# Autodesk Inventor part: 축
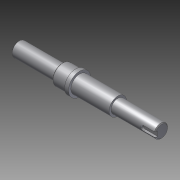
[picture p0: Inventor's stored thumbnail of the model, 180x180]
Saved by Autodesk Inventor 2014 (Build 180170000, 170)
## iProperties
Company: 한국ATC센터
Created: 2014-03
Part Number: 축
Document SubType Name: Modeling
Designer: KYOUNG IL JANG
Density: 1 g/cm^3
Material: 일반
Appearance: 기본값
Author: KYOUNG IL JANG
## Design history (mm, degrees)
sketch "스케치1"
  geometry: L1 (-102, 80)-(78, 80); L2 (-30.3, 106)-(-30.3, 54) reference; L3 (23, 99.7)-(23, 60.3) reference; L4 (-102, 80)-(-102, 89); L5 (-102, 89)-(-47, 89); L6 (-47, 89)-(-47, 92.5); L7 (-47, 92.5)-(-30, 92.5); L8 (-25, 94)-(-25, 91); L9 (-25, 91)-(23, 91); L10 (23, 91)-(23, 88.5); L11 (23, 88.5)-(78, 88.5); L12 (78, 88.5)-(78, 80); L13 (-30, 94)-(-25, 94); L14 (-31, 92.5)-(-44, 92.5) reference; L15 (-30, 105)-(-30, 55) reference; L16 (-30, 94)-(-30, 92.5); L17 (-68, 65.3)-(-68, 94.7) reference; L18 (-96, 89)-(-96, 85.5); L19 (-96, 85.5)-(-74, 85.5); L20 (-74, 85.5)-(-74, 89); L21 (60, 75)-(83, 75); L22 (83, 75)-(83, 71.5); L23 (83, 71.5)-(60, 71.5); L24 (60, 71.5)-(60, 75); 2 further points
  constraints: 40 end point, 12 perpendicular, 7 point on line, 3 horizontal, 3 parallel, 2 collinear, 1 midpoint, 1 other
  dimensions: "d0" = 18 diameter of L5 L1; "d1" = 17 distance of L6.end L7.end; "d2" = 5 distance of L13.start L8.start; "d3" = 28 diameter of L13 L1; "d4" = 22 diameter of L9 L1; "d5" = 17 diameter of L11 L1; "d8" = 34 distance between parallel lines of L17 L4; "d9" = 55 distance of L10.end L11.end; "d11" = 3.5 distance between parallel lines of L19 L5; "d12" = 22 distance between parallel lines of L20 L18; "d13" = 6 distance between parallel lines of L18 L4; "d14" = 17 diameter of L23 L1 (= d5); "d15" = 3.5 distance of L23.end L21.start (= d11); "d16" = 18 distance between parallel lines of L24 L12; "d17" = 23 distance of L22.end L23.end
  node "참조1"
  node "참조2"
  node "참조3"
  node "참조4"
revolve "회전1" stored, may be unused: angle "d10" = 90 deg
extrude "돌출1" cut sketch "스케치1" stored distance "d18" = 6; taper "d19" = 0 deg
fillet "모깎기1" dims "d20" = 3
chamfer "모따기1" distance "d21" = 1; stored, may be unused: second distance "d22" = 2, angle "d23" = 45 deg
node "솔리드1"
